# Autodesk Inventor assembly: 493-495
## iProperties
Author: Administrator
Created: 2002-03
Part Number: 493-495
Document SubType Name: Assembly
Designer: Administrator
Control State: 0
Master: False
Checked Out: False
PropertySet Name: Design Tracking Control
Shininess: 64.0
Angle Display Precision: 2
Document Length Units: 11272
Document Angle Units: 11286
Document Time Units: 11279
Document Mass Units: 11290
Document Length Units Precision: 3
Document Angle Units Precision: 2
Compacted: True
PropertySet Name: _Private Model Information
Density: 0.0
Volumn: 0.0
Area: 0.0
PropertySet Name: Model Information
